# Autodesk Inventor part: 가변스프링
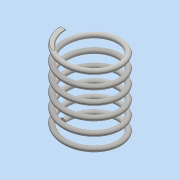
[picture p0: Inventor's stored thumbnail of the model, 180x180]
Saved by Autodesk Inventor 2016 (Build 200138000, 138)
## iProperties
Created: 2018-11
Part Number: 가변스프링
Material: 일반
Document SubType Name: Modeling
Designer: user
Density: 1 g/cm^3
Appearance: 기본값
Mass: 10.5248 g
Surface Area: 106.476 cm^2
Volume: 10.5248 cm^3
Author: user
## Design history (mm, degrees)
sketch "스케치1"
  geometry: L1 (0, 0)-(22.5, 0); L2 (22.5, 0)-(22.5, 67.25); L3 (22.5, 67.25)-(0, 67.25); L4 (0, 67.25)-(0, 0); C1 r 2 at (22.5, 0)
  constraints: 8 end point, 2 parallel, 1 centre point, 1 coincident, 1 horizontal, 1 perpendicular
  dimensions: "d0" = 67.25 distance of L3.end L1.start (derived); "d1" = 4 diameter of C1; "d2" = 45 diameter of L2 L4
feature "코일1" sketch "스케치1" pitch "d3" = 10; turns "d5" = 6; dims "d4" = 67.25 (= d0), "d6" = 0, angle "d7" = 90 deg, angle "d8" = 90 deg, "d9" = 0, "d10" = 0
sketch "스케치2"
  geometry: L1 (84.1, 67.25)-(-84.1, 67.25); L2 (-84.1, 67.25)-(-84.1, 0); L3 (-84.1, 0)-(84.1, 0); L4 (84.1, 0)-(84.1, 67.25); 2 further points
  constraints: 8 end point, 2 parallel, 1 coincident, 1 horizontal, 1 midpoint, 1 perpendicular
  dimensions: "d11" = 168.19974 distance between parallel lines of L2 L4; "d12" = 67.25 distance between parallel lines of L3 L1 (= d0)
extrude "돌출1" sketch "스케치2" stored distance "d13" = 100; taper "d14" = 0 deg
node "솔리드1"
